(* Logix 5000 project; controller MOXA_SWITCH_DEMO vendor 1 type 14 code 77 rev 18.12; software revision 18.01 *)

TASK MainTask (continuous, watchdog 500 ms) : MainProgram

MODULES
   Controller : vendor 1 type 14 code 77 (CompactLogixL32EController 0, rev 18.12)
      LocalENB : 1769-L32E Ethernet Port (CompactLogixL32Ethernet 1, rev 18.11)
         MOXA_SWITCH : ETHERNET-MODULE (Ethernet 192.168.34.253, rev 1.1, Output RPI 10 ms)
      Local : CompactBus (CompactVirtualAdapter 3, rev 18.11)
END_MODULES

TYPE MOXA_Ethernet_Link_Object_v0 :   // class 0xf6
STRUCT
   Interface_Speed : DINT;   // Interface speed currently in use. Speed in Mbps (e.g., 0, 10, 100, 1000, etc.)
   Interface_Flags : MOXA_Interface_Object_Flags_v0;   // Interface status flags
   Physical_Address : SINT[6];   // MAC layer address
   InOctets : DINT;   // Octets received on the interface
   InUcastPackets : DINT;   // Unicast packets received on the interface
   InNucastPackets : DINT;   // Non-unicast packets received on the interface
   InDiscards : DINT;   // Inbound packets received on the interface but discarded
   InErrors : DINT;   // Inbound packets that contain errors (does not include In Discards)
   OutOctets : DINT;   // Octets sent on the interface
   OutUcastPackets : DINT;   // Unicast packets sent on the interface
   OutNucastPackets : DINT;   // Non-unicast packets sent on the interface
   OutDiscards : DINT;   // Outbound packets discarded
   OutErrors : DINT;   // Outbound packets that contain errors
   Alignment_Errors : DINT;   // Frames received that are not an integral number of octets in length
   FCS_Errors : DINT;   // Frames received that do not pass the FCS check
   Single_Collisions : DINT;   // Successfully transmitted frames which experienced exactly one collision
   Multiple_Collisions : DINT;   // Successfully transmitted frames which experienced more than one collision
   SQE_Test_Errors : DINT;   // Number of times SQE test error message is generated
   Deferred_Transmissions : DINT;   // Frames for which first transmission attempt is delayed because the medium is busy
   Late_Collisions : DINT;   // Number of times a collision is detected later than 512 bit- times into the transmission of a packet
   Excessive_Collisions : DINT;   // Frames for which transmission fails due to excessive collisions
   MAC_Transmit_Errors : DINT;   // Frames for which transmission fails due to an internal MAC sublayer transmit error
   Carrier_Sense_Errors : DINT;   // Times that the carrier sense condition was lost or never asserted when attempting to transmit a frame
   Frame_Too_Long : DINT;   // Frames received that exceed the maximum permitted frame size
   MAC_Receive_Errors : DINT;   // Frames for which reception on an interface fails due to an internal MAC sublayer receive error
   Control_Bits : INT;   // 0 Auto-negotiate 0 indicates 802.3 link auto-negotiation is disabled. 1 indicates auto-negotiation is enabled.
   Forced_Interface_Speed : INT;   // Speed at which the interface shall be forced to operate. Speed in Mbps (10, 100, 1000, etc.)
   Interface_Label : STRING;   // Label like "TX5"
   Interface_Port_Index : DINT;   // port index
   Interface_Port_Description : STRING;   // Port description
   Broascast_Storm_Protection : SINT;   // Only BCM
   Interface_Utilization : SINT;   // Percentage of entire interface bandwidth being used (0-100)
   Utilization_Alarm_Upper_Threshold : SINT;   // Upper percentage at which to declare a utilization alarm (0-100).
   Utilization_Alarm_Lower_Threshold : SINT;   // Lower percentage at which to declare a utilization alarm (0-100).
   Port_Link_Alarm : SINT;   // 0: Ignore 1:On (Relay 1) 2:On (Relay 2) 3:Off (Relay1) 4:Off (Relay2)
   Port_TrafficOverload_Alarm : SINT;   // 0:Disable 1:Enable(Relay 1) 2:Enable(Relay 2)
   Tx_Unicast_Packet_Rate : DINT;   // number of TX unicast packets per second.
   Rx_Unicast_Packet_Rate : DINT;   // number of RX unicast packets per second.
   Tx_Multicast_Packet_Rate : DINT;   // number of TX multicast packets per second.
   Rx_Multicast_Packet_Rate : DINT;   // number of RX multicast packets per second.
   Tx_Broadcast_Packet_Rate : DINT;   // number of TX broadcast packets per second.
   Rx_Broadcast_Packet_Rate : DINT;   // number of RX broadcast packets per second.
   Tx_Multicast_Packet : DINT;   // Total number of Tx multicast packets
   Rx_Multicast_Packet : DINT;   // Total number of Rx multicast packets
   Tx_Broadcast_Packet : DINT;   // Totalnumber of Tx Multicast packets
   Rx_Broadcast_Packet : DINT;   // Total number of Rx broadcast packets
   Redundant_Port_Status : DINT;   // Bit 0 = Disable, Bit 1 =Not Red. port, Bit 2 = Link down, Bit 3 = Blocking, Bit 4 = Learning, Bit 5 = Forwarding
END_STRUCT
END_TYPE

TYPE MOXA_HMI_Set_Object_v0 :
STRUCT
   Control_Bits : INT;
   Speed_Duplex : SINT;
   Port_Enable : SINT;   // 1=enable, 2=disable
   Enter_Port_Enable : BOOL;   // Set to 1 to trigger port enable/disable change
   Reset_mib_counter : SINT;   // reset mib counter
   Reset_to_default : SINT;   // Restart and reset to default
   Select_Port : INT;   // current port select on FT View
   Enter_Port_Setting : BOOL;
   Enter_Reset_Setting : BOOL;
END_STRUCT
END_TYPE

TYPE MOXA_Identity_Object_v0 :   // class 0x01
STRUCT
   Vendor_ID : INT;   // ODVA Vendor ID. N-Tron = 991
   Device_Type : INT;   // 0x307, "Managed Ethernet Switch"
   Product_Code : INT;   // EDS-405A=0x0006 EDS-408A=0x0007
   Major_Revision : SINT;   // Major revision of the item the Identity Object represents
   Minor_Revision : SINT;   // Minor revision of the item the Identity Object represents
   Serial_Number : DINT;   // Serial number of device
   Product_Name : STRING;   // Human readable identification. Switch model number. Ex: EDS-508A
   Assigned_Name : MOXA_String_1024;   // User assigned switch name.
   Geographic_Location : MOXA_String_1024;   // This is the user assigned switch location.
END_STRUCT
END_TYPE

TYPE MOXA_Interface_Object_Flags_v0 :   // reference to Ethernet Link object
STRUCT
   Link_Status : BOOL;   // 0-inactive, 1-active
   Duplex : BOOL;   // 0-half, 1-full
   Negotiation_Status_1 : BOOL;
   Negotiation_Status_2 : BOOL;
   Negotiation_Status_3 : BOOL;
   Manual_Setting_Requires_Reset : BOOL;
   Local_Hardware_Fault : BOOL;
END_STRUCT
END_TYPE

TYPE MOXA_Object_Data_v0 :   // This UDT contains various information that appears on an HMI display. Some information applies to the switch, and some applies to the selected port (copied, or derived from, the port Ethernet_Link data) because FactoryTalk can not access array elements.
STRUCT
   IP_Address : MOXA_String_32;
   Network_Mask : MOXA_String_32;
   Control_Bits : INT;
   Port_Speed : DINT;   // 1=10/half, 2=10/full, 3=100/half, 4=100/Full, 100=auto negotiate,
   Port_Interface_Flag : MOXA_Interface_Object_Flags_v0;
   MAC_Address : MOXA_String_32;
   Error_Counter : DINT;
   Port_Index : DINT;
   TX_Unicast_Packet_Rate : DINT;   // begin port specific data
   RX_Unicast_Packet_Rate : DINT;
   TX_Multicast_Packet_Rate : DINT;
   RX_Multicast_Packet_Rate : DINT;
   TX_Broadcast_Packet_Rate : DINT;
   RX_Broadcast_Packet_Rate : DINT;
   Redundant_Port_Role : DINT;   // redundant port role
   System_Fault : MOXA_System_Fault_v0;
   CPU_Usage : SINT;
   Redundant_Port_Status : DINT;   // bit 0: Disable Bit 1: Not Redundant Bit 2: Link down Bit 3: Blocking Bit 4: Learning Bit 5: Forwarding
   Software_Version : STRING;   // Show software version
   Port : INT;
   Interface_Utilization : SINT;
   Tx_Packet_Error : DINT;
   Rx_Packet_Error : DINT;
END_STRUCT
END_TYPE

TYPE MOXA_String_1024 :   // string type
STRUCT
   LEN : DINT;
   DATA : SINT[1024];
END_STRUCT
END_TYPE

TYPE MOXA_String_32 :   // string type; display the ip address, subnet mask, gateway address
STRUCT
   LEN : DINT;
   DATA : SINT[32];
END_STRUCT
END_TYPE

TYPE MOXA_Switch_In_v0 :   // switch input
STRUCT
   System_Fault : MOXA_System_Fault_v0;   // Status of various system faults.
   Link_Status : DINT;
   Link_Status_TX1 : BOOL;
   Link_Status_TX2 : BOOL;
   Link_Status_TX3 : BOOL;
   Link_Status_TX4 : BOOL;
   Link_Status_TX5 : BOOL;
   Link_Status_TX6 : BOOL;
   Link_Status_TX7 : BOOL;
   Link_Status_TX8 : BOOL;
   CPU_Utilization : SINT;   // Percent of CPU usage, 0-100
   Port_Exist : DINT;
   Port_Exist_1 : DINT;
   Port_Exist_2 : DINT;
   Port_Exist_3 : DINT;
   Port_Exist_4 : DINT;
   Port_Exist_5 : DINT;
   Port_Exist_6 : DINT;
   Port_Exist_7 : DINT;
   Port_Exist_8 : DINT;
END_STRUCT
END_TYPE

TYPE MOXA_Switch_Parameter :
STRUCT
   Switch_Input : MOXA_Switch_In_v0;   // recieve message from switch
   Switch_Output : DINT;   // send message from switch
   Switch_Idnetity : MOXA_Identity_Object_v0;
   Switch_TCPIP : MOXA_TCPIP_Interface_Object_v0;
   Switch_Vendor : MOXA_Vendor_Object_v0;
   Switch_Ethernet_Link : MOXA_Ethernet_Link_Object_v0[25];
   Switch_Data : MOXA_Object_Data_v0;
   Switch_HMI_Set : MOXA_HMI_Set_Object_v0;
END_STRUCT
END_TYPE

TYPE MOXA_System_Fault_v0 :   // reference to Switch object
STRUCT
   Fault : DINT;
   Turbo_Ring_Turbo_Ring_2 : BOOL;   // Reserved value 0: OK value 1: Fail
   Dongle_Configuration_Invalid : BOOL;   // Reserved value 0: OK value 1: Fail
   Port_Utilization_Alarm : BOOL;   // Value 0: no Alarm
   Port_Link_Up : BOOL;   // Value 0: no Alarm Value 1: Alarm
   Port_Link_Down : BOOL;   // Value 0: no Alarm Value 1: Alarm
   Turbo_Rinh_Break : BOOL;   // Ring Master Only Value 0: no Alarm Value 1: Alarm
   Power_Input_1_Fail : BOOL;   // Value 0: no Alarm Value 1: Alarm
   Power_Input_2_Fail : BOOL;   // Value 0: no Alarm Value 1: Alarm
   DI_1_Off : BOOL;   // Value 0: no Alarm Value 1: Alarm
   DI_1_On : BOOL;   // Value 0: no Alarm Value 1: Alarm
   DI_2_Off : BOOL;   // Value 0: no Alarm Value 1: Alarm
   DI_2_On : BOOL;   // Value 0: no Alarm Value 1: Alarm
   ABC_detect : BOOL;   // Value 0: no detect Value 1: detect
   Power_Supply_1 : BOOL;   // Value 0: off Value 1: on
   Power_Supply_2 : BOOL;   // Value 0: off Value 1: on
END_STRUCT
END_TYPE

TYPE MOXA_TCPIP_Interface_Object_v0 :   // class 0xf5
STRUCT
   Status : DINT;   // Interface Status:
   Configuration_Capability : DINT;   // Interface capability flags
   Configuration_Control : DINT;   // Interface control flags
   Path_Size : INT;   // Size of Path
   Object_Path_1 : INT;   // Logical segments identifying the physical link object
   Object_Path_2 : INT;   // Logical segments identifying the physical link object
   IP_Address : DINT;   // The device’s IP address.
   Network_Mask : DINT;   // The device’s network mask
   Gateway_Address : DINT;   // Default gateway address
   Name_Server_1 : DINT;   // Primary name server
   Name_Server_2 : DINT;   // Secondary name server
   Domain_Name : STRING;   // Default domain name
   Host_Name : STRING;   // Host Name
END_STRUCT
END_TYPE

TYPE MOXA_Vendor_Object_v0 :   // class 0x404
STRUCT
   System_Firmware_Version : DINT;   // Switch Firmware Version
   System_Fault_Status : DINT;   // Switch Fault Status
   Switch_Port_Number : SINT;   // Switch max port number
   Port_Exist : DINT[2];   // switch per port exist
   Port_Enbale : DINT[2];   // Switch Per Port Exist 0:Enable 1:Disable
   Port_Link_Status : DINT[2];   // Switch Per Port Link Status
   IGMP_Snooping : SINT;   // IGMP Snooping Enable: 0: disable 1: enable
   Query_Interval : DINT;   // Query Interval range from 20~600 sec
   IGMP_Enhanced_Mode : SINT;   // IGMP Enhanced Mode 0: Disable (default) 1: Enable
   Relay_1 : SINT;   // Override relay warning setting 0:Disable (default) 1: Enable
   Relay_2 : SINT;   // Override relay warning setting 0:Disable (default) 1: Enable
   Power_1_Relay_Warning : SINT;   // Power input 1 failure (on -> off) 0: Disable (default) 1: Enable(relay 1) 2: Enable(relay 2)
   Power_2_Relay_Warning : SINT;   // Power input 2 failure (on -> off) 0: Disable (default) 1: Enable(relay 1) 2: Enable(relay 2)
   DI_1_Off_Relay_Warning : SINT;   // DI 1 (off) 0: disable (default) 1: enable(relay 1) 2: enable(relay 2)
   DI_1_On_Relay_Warning : SINT;   // DI 1 (on) 0: disable (default) 1: enable(relay 1) 2: enable(relay 2)
   DI_2_Off_Relay_Warning : SINT;   // DI 2 (off) 0: disable (default) 1: enable(relay 1) 2: enable(relay 2)
   DI_2_On_Relay_Warning : SINT;   // DI 2 (on) 0: disable (default) 1: enable(relay 1) 2: enable(relay 2)
   Turbo_Ring_Break_Relay_Warning : SINT;   // Turbo Ring Break (Ring MAster Only ) 0: diable (default) 1: enable (relay 1) 2:enable (relay 2)
   CPU_Usage : SINT;   // Percent of usage (0-100)
   Device_Up_Time : DINT;   // Number of seconds since device was powered up.
   Reset_Mib_Counter : SINT;   // Reset port MIB counters.
   Redundant_Device_Mode : DINT;   // Bit 0: RSTP Bit 1: turbo ring Bit 2: turbo ring v2 Bit 3: turbo chain Bit 4: MSTP
END_STRUCT
END_TYPE

ADD_ON_INSTRUCTION AOI_MOXA_SWITCH_v1_0_0   (* revision 1.0, vendor MOXA Corporation *)
// the AOI of MOXA switch
// Copyright MOXA Corp. 2011
// Version: 1.0.0
// Date: December 23, 2011
VAR_IN_OUT
   Switch_Input : DINT[5]; {required}   // The module defined array representing the input assembly
   Switch_Output : DINT[1]; {required}   // The module defined array representing the output assembly
   Switch_Parameter : MOXA_Switch_Parameter; {required}
   Get_AllMessage : MESSAGE; {required}   // Message to retrieve parameters from CIP object what service is get all
   Set_Message : MESSAGE; {required}   // Message to send parameters from CIP object
   storage : SINT[200]; {required}   // Internal use: storage for explicit messaging responses
   Set_Data : INT[2]; {required}
   Get_SingMessage : MESSAGE; {required}   // Message to retrieve parameters from CIP object what service is get single
   storage_single : SINT[70]; {required}
END_VAR
VAR
   copyTimer : TIMER := (PRE := 5000); {access None}   // for loop every 5 sec
   timer_io : TIMER := (PRE := 50); {access None}
   SelectCounter : COUNTER := (PRE := 150); {access None}
   port_index : DINT; {access None}
   IP_Address_StringArray : STRING[4]; {access None}
   Network_Mask_StringArray : STRING[4]; {access None}
   IP_Address_OctetArray : DINT[4]; {access None}
   Network_Mask_OctetArray : DINT[4]; {access None}
   MAC_OctetArray : DINT[12]; {access None}
   MAC_StringArray : STRING[12]; {access None}
   timer_explicit : TIMER := (PRE := 100); {access None}
   Update_flag : BOOL; {access None}   // Update flag. start to read MSG
   punctuation_marks : STRING; {access None}
   String_Len : DINT;
   GetVendorObject : INT;
   portnum_index : SINT;
   Port_Enable_setting : INT; {access None}
   AttriSelectCounter : INT; {access None}
   Firmware_Version_Object : DINT;
   ons_getall : BOOL; {access None}
   ons_getsingle : BOOL; {access None}
   Debug : DINT; {access None}
   timer_ethernet : TIMER := (PRE := 200); {access None}
   temp_data : DINT;
   MAC_Counter : DINT; {access None}
   b_SetPortMSG : BOOL; {access None}
   b_SetMibMSG : BOOL; {access None}
   b_SetResetMSG : BOOL; {access None}
   Software_Version_temp : SINT[2]; {access None}
   Software_Version_String : STRING[2]; {access None}
   b_SetPortEnable : BOOL; {access None}
   b_SetPortDuplex : BOOL; {access None}
   InterfaceControlBit : INT; {access None}
   InterfaceSpeedDuplex : INT; {access None}
   b_SetMSG : BOOL; {access None}
   InterfacePortEnable : INT; {access None}
END_VAR

ROUTINE Logic   (* ladder *)
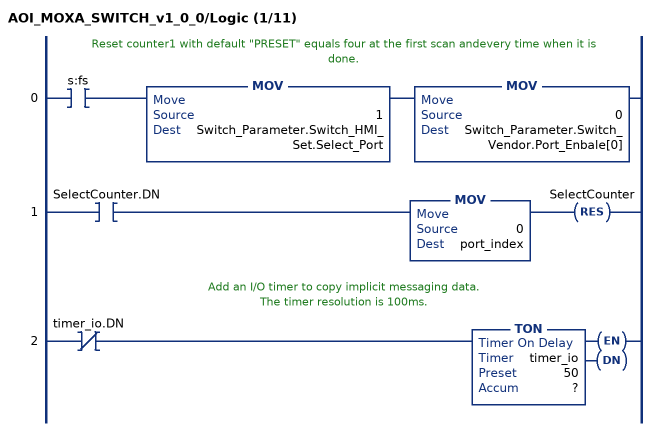
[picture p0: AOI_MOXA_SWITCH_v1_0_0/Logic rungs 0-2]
   // Reset counter1 with default "PRESET" equals four at the first scan andevery time when it is done.
   0: XIC(s:fs)MOV(1,Switch_Parameter.Switch_HMI_Set.Select_Port)MOV(0,Switch_Parameter.Switch_Vendor.Port_Enbale[0]);
   1: XIC(SelectCounter.DN)MOV(0,port_index)RES(SelectCounter);
   // Add an I/O timer to copy implicit messaging data.
   // The timer resolution is 100ms.
   2: XIO(timer_io.DN)TON(timer_io,?,?);
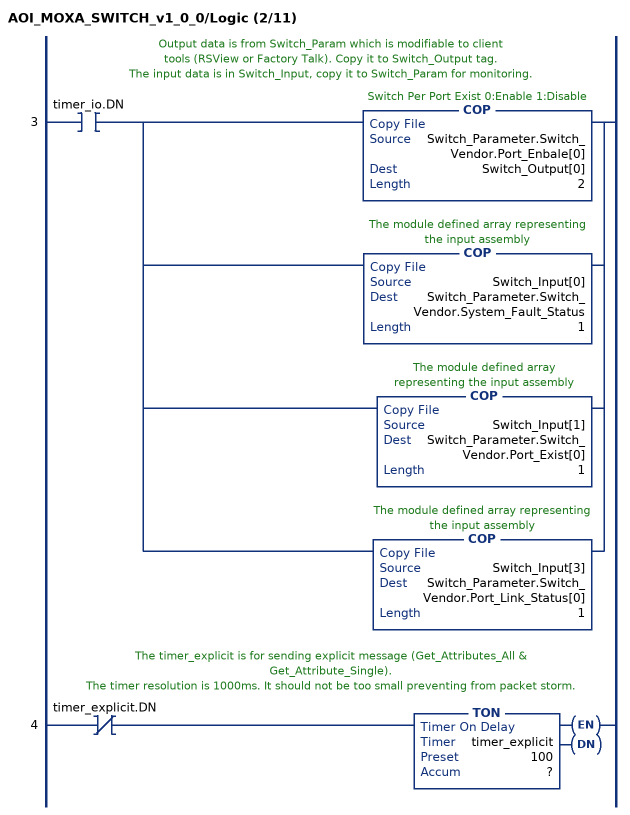
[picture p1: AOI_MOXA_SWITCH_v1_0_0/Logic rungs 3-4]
   // Output data is from Switch_Param which is modifiable to client
   //  tools (RSView or Factory Talk). Copy it to Switch_Output tag.
   // The input data is in Switch_Input, copy it to Switch_Param for monitoring.
   3: XIC(timer_io.DN)[COP(Switch_Parameter.Switch_Vendor.Port_Enbale[0],Switch_Output[0],2) ,COP(Switch_Input[0],Switch_Parameter.Switch_Vendor.System_Fault_Status,1) ,COP(Switch_Input[1],Switch_Parameter.Switch_Vendor.Port_Exist[0],1) ,COP(Switch_Input[3],Switch_Parameter.Switch_Vendor.Port_Link_Status[0],1) ];
   // The timer_explicit is for sending explicit message (Get_Attributes_All & Get_Attribute_Single).
   // The timer resolution is 1000ms. It should not be too small preventing from packet storm.
   4: XIO(timer_explicit.DN)TON(timer_explicit,?,?);
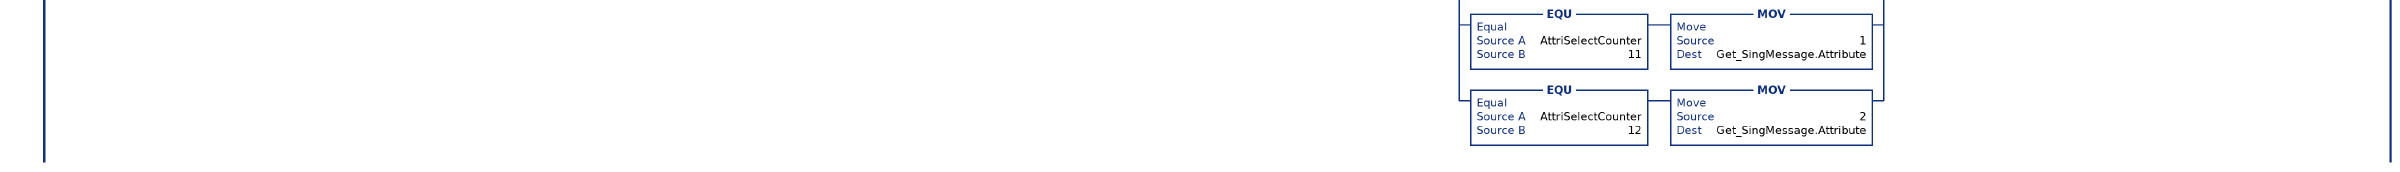
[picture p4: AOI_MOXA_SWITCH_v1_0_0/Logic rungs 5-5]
   // If ClassSelectCounter.ACC== 1, send GAA of Identity object (Class ID = 1).
   // If ClassSelectCounter.ACC== 2, send GAA of TCP/IP object (Class ID = 245).
   // If ClassSelectCounter.ACC== 3, send GAA of Vendor object (class ID = 1028)
   // If ClassSelectCounter.ACC==4~15, snd GAA of Ethernet Link object(Class ID = 246)
   5: XIC(timer_explicit.DN)CTU(SelectCounter,?,?)[LIM(1,SelectCounter.ACC,2) MOV(1,Get_AllMessage.Instance) MOV(1,Get_AllMessage.Attribute) [EQU(SelectCounter.ACC,1) MOV(1,Get_AllMessage.Class) ,EQU(SelectCounter.ACC,2) MOV(245,Get_AllMessage.Class) ] FLL(0,storage[0],200) MSG(Get_AllMessage) ,LIM(3,SelectCounter.ACC,11) MOV(1028,Get_SingMessage.Class) MOV(1,Get_SingMessage.Instance) [EQU(SelectCounter.ACC,3) MOV(1,Get_SingMessage.Attribute) ,EQU(SelectCounter.ACC,4) MOV(2,Get_SingMessage.Attribute) ,EQU(SelectCounter.ACC,5) MOV(5,Get_SingMessage.Attribute) ,EQU(SelectCounter.ACC,6) MOV(6,Get_SingMessage.Attribute) ,EQU(SelectCounter.ACC,7) MOV(8,Get_SingMessage.Attribute) ,EQU(SelectCounter.ACC,8) MOV(9,Get_SingMessage.Attribute) ,EQU(SelectCounter.ACC,9) MOV(23,Get_SingMessage.Attribute) ,EQU(SelectCounter.ACC,10) MOV(25,Get_SingMessage.Attribute) ,EQU(SelectCounter.ACC,11) MOV(26,Get_SingMessage.Attribute) ] FLL(0,storage[0],200) MSG(Get_SingMessage) ,LIM(12,SelectCounter.ACC,150) SUB(SelectCounter.ACC,12,AttriSelectCounter) DIV(AttriSelectCounter,13,temp_data) ADD(temp_data,1,portnum_index) MOD(AttriSelectCounter,13,AttriSelectCounter) MOV(246,Get_SingMessage.Class) MOV(portnum_index,Get_SingMessage.Instance) [EQU(AttriSelectCounter,0) MOV(3,Get_SingMessage.Attribute) ,EQU(AttriSelectCounter,1) MOV(4,Get_SingMessage.Attribute) ,EQU(AttriSelectCounter,2) MOV(6,Get_SingMessage.Attribute) ,EQU(AttriSelectCounter,3) MOV(103,Get_SingMessage.Attribute) ,EQU(AttriSelectCounter,4) MOV(108,Get_SingMessage.Attribute) ,EQU(AttriSelectCounter,5) MOV(109,Get_SingMessage.Attribute) ,EQU(AttriSelectCounter,6) MOV(110,Get_SingMessage.Attribute) ,EQU(AttriSelectCounter,7) MOV(111,Get_SingMessage.Attribute) ,EQU(AttriSelectCounter,8) MOV(112,Get_SingMessage.Attribute) ,EQU(AttriSelectCounter,9) MOV(113,Get_SingMessage.Attribute) ,EQU(AttriSelectCounter,10) MOV(118,Get_SingMessage.Attribute) ,EQU(AttriSelectCounter,11) MOV(1,Get_SingMessage.Attribute) ,EQU(AttriSelectCounter,12) MOV(2,Get_SingMessage.Attribute) ] FLL(0,storage_single[0],70) MSG(Get_SingMessage) ];
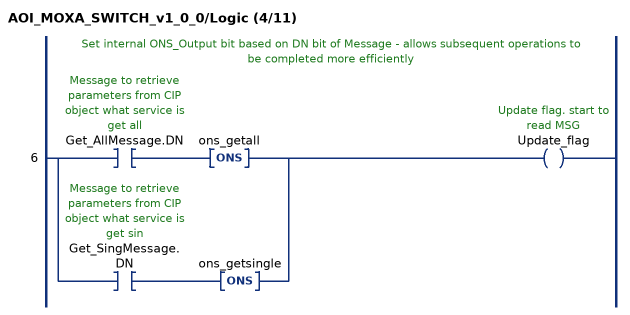
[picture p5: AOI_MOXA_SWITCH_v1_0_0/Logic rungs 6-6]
   // Set internal ONS_Output bit based on DN bit of Message - allows subsequent operations to be completed more efficiently
   6: [XIC(Get_AllMessage.DN) ONS(ons_getall) ,XIC(Get_SingMessage.DN) ONS(ons_getsingle) ]OTE(Update_flag);
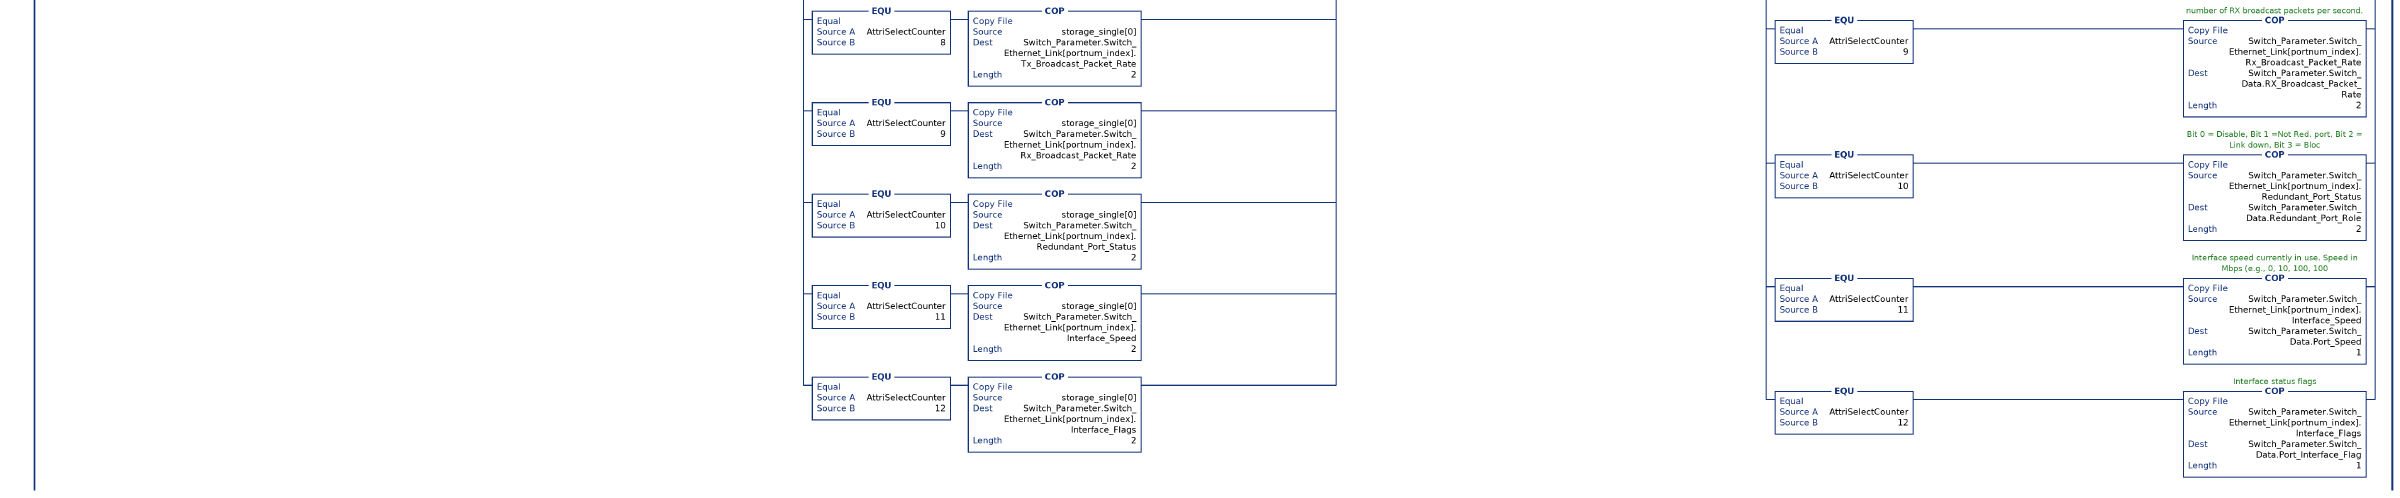
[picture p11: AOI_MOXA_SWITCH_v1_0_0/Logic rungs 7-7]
   // Copy results of Get Attribute All
   // If counter = 1: Identity Object - Class 1, Instance 1, Attribute 1
   // If counter = 2: TCP/IP Interface Object, Class 245, Instance 1, Attribute 1
   // If counter = 3 : Vendor Object, Class 1028, Instance 1, Attribute 1
   // If counter = 4~15 : EtherNet Link Object, Class 246, Instance 1 to 12 , Attribute 1 - EthernetLink[1-12]
   7: XIC(Update_flag)[EQU(SelectCounter.ACC,1) [COP(storage[0],Switch_Parameter.Switch_Idnetity.Vendor_ID,1) ,COP(storage[2],Switch_Parameter.Switch_Idnetity.Device_Type,1) ,COP(storage[4],Switch_Parameter.Switch_Idnetity.Product_Code,1) ,COP(storage[10],Switch_Parameter.Switch_Idnetity.Serial_Number,2) ,MOV(storage[14],String_Len) MOV(String_Len,Switch_Parameter.Switch_Idnetity.Product_Name.LEN) FLL(0,Switch_Parameter.Switch_Idnetity.Product_Name.DATA[0],28) COP(storage[15],Switch_Parameter.Switch_Idnetity.Product_Name.DATA[0],String_Len) ] ,EQU(SelectCounter.ACC,2) [COP(storage[18],Switch_Parameter.Switch_TCPIP.IP_Address,2) ,COP(storage[22],Switch_Parameter.Switch_TCPIP.Network_Mask,2) ,MOV(0,String_Len) COP(storage[38],String_Len,1) ADD(String_Len,40,String_Len) ,COP(storage[40],Switch_Parameter.Switch_TCPIP.Host_Name.LEN,1) ADD(String_Len,2,String_Len) ,COP(storage[42],Switch_Parameter.Switch_TCPIP.Host_Name.DATA[0],64) ] ,LIM(3,SelectCounter.ACC,11) [EQU(SelectCounter.ACC,3) COP(storage_single[0],Switch_Parameter.Switch_Vendor.System_Firmware_Version,2) ,EQU(SelectCounter.ACC,4) COP(storage_single[0],Switch_Parameter.Switch_Vendor.System_Fault_Status,2) ,EQU(SelectCounter.ACC,5) COP(storage_single[0],Switch_Parameter.Switch_Vendor.Port_Enbale[0],4) ,EQU(SelectCounter.ACC,6) COP(storage_single[0],Switch_Parameter.Switch_Vendor.Port_Link_Status[0],4) ,EQU(SelectCounter.ACC,7) COP(storage_single[0],Switch_Parameter.Switch_Vendor.Query_Interval,2) ,EQU(SelectCounter.ACC,8) COP(storage_single[0],Switch_Parameter.Switch_Vendor.IGMP_Enhanced_Mode,1) ,EQU(SelectCounter.ACC,9) COP(storage_single[0],Switch_Parameter.Switch_Vendor.CPU_Usage,1) ,EQU(SelectCounter.ACC,10) COP(storage_single[0],Switch_Parameter.Switch_Vendor.Reset_Mib_Counter,1) ,EQU(SelectCounter.ACC,11) COP(storage_single[0],Switch_Parameter.Switch_Vendor.Redundant_Device_Mode,2) ] ,LIM(12,SelectCounter.ACC,150) SUB(SelectCounter.ACC,12,AttriSelectCounter) DIV(AttriSelectCounter,13,temp_data) ADD(temp_data,1,portnum_index) MOD(AttriSelectCounter,13,AttriSelectCounter) [EQU(AttriSelectCounter,0) COP(storage_single[0],Switch_Parameter.Switch_Ethernet_Link[portnum_index].Physical_Address[0],6) ,EQU(AttriSelectCounter,1) [COP(storage_single[16],Switch_Parameter.Switch_Ethernet_Link[portnum_index].InErrors,2) ,COP(storage_single[40],Switch_Parameter.Switch_Ethernet_Link[portnum_index].OutErrors,2) ] ,EQU(AttriSelectCounter,2) [LIM(0,storage_single[0],2) COP(storage_single[0],Switch_Parameter.Switch_Ethernet_Link[portnum_index].Control_Bits,1) ,[EQU(storage_single[2],0) ,EQU(storage_single[2],10) ,EQU(storage_single[2],100) ,EQU(storage_single[2],1000) ] COP(storage_single[2],Switch_Parameter.Switch_Ethernet_Link[portnum_index].Forced_Interface_Speed,1) ] ,EQU(AttriSelectCounter,3) COP(storage_single[0],Switch_Parameter.Switch_Ethernet_Link[portnum_index].Interface_Utilization,1) ,EQU(AttriSelectCounter,4) COP(storage_single[0],Switch_Parameter.Switch_Ethernet_Link[portnum_index].Tx_Unicast_Packet_Rate,1) ,EQU(AttriSelectCounter,5) COP(storage_single[0],Switch_Parameter.Switch_Ethernet_Link[portnum_index].Rx_Unicast_Packet_Rate,1) ,EQU(AttriSelectCounter,6) COP(storage_single[0],Switch_Parameter.Switch_Ethernet_Link[portnum_index].Tx_Multicast_Packet_Rate,2) ,EQU(AttriSelectCounter,7) COP(storage_single[0],Switch_Parameter.Switch_Ethernet_Link[portnum_index].Rx_Multicast_Packet_Rate,2) ,EQU(AttriSelectCounter,8) COP(storage_single[0],Switch_Parameter.Switch_Ethernet_Link[portnum_index].Tx_Broadcast_Packet_Rate,2) ,EQU(AttriSelectCounter,9) COP(storage_single[0],Switch_Parameter.Switch_Ethernet_Link[portnum_index].Rx_Broadcast_Packet_Rate,2) ,EQU(AttriSelectCounter,10) COP(storage_single[0],Switch_Parameter.Switch_Ethernet_Link[portnum_index].Redundant_Port_Status,2) ,EQU(AttriSelectCounter,11) COP(storage_single[0],Switch_Parameter.Switch_Ethernet_Link[portnum_index].Interface_Speed,2) ,EQU(AttriSelectCounter,12) COP(storage_single[0],Switch_Parameter.Switch_Ethernet_Link[portnum_index].Interface_Flags,2) ] EQU(Switch_Parameter.Switch_HMI_Set.Select_Port,portnum_index) MOV(Switch_Parameter.Switch_HMI_Set.Select_Port,Switch_Parameter.Switch_Data.Port) [EQU(AttriSelectCounter,1) [COP(Switch_Parameter.Switch_Ethernet_Link[portnum_index].InErrors,Switch_Parameter.Switch_Data.Error_Counter,2) ADD(Switch_Parameter.Switch_Ethernet_Link[portnum_index].OutErrors,Switch_Parameter.Switch_Data.Error_Counter,Switch_Parameter.Switch_Data.Error_Counter) ,COP(Switch_Parameter.Switch_Ethernet_Link[portnum_index].InErrors,Switch_Parameter.Switch_Data.Rx_Packet_Error,2) COP(Switch_Parameter.Switch_Ethernet_Link[portnum_index].OutErrors,Switch_Parameter.Switch_Data.Rx_Packet_Error,2) ] ,EQU(AttriSelectCounter,2) COP(Switch_Parameter.Switch_Ethernet_Link[portnum_index].Control_Bits,Switch_Parameter.Switch_Data.Control_Bits,1) ,EQU(AttriSelectCounter,3) COP(Switch_Parameter.Switch_Ethernet_Link[portnum_index].Interface_Utilization,Switch_Parameter.Switch_Data.Interface_Utilization,1) ,EQU(AttriSelectCounter,4) COP(Switch_Parameter.Switch_Ethernet_Link[portnum_index].Tx_Unicast_Packet_Rate,Switch_Parameter.Switch_Data.TX_Unicast_Packet_Rate,2) ,EQU(AttriSelectCounter,5) COP(Switch_Parameter.Switch_Ethernet_Link[portnum_index].Rx_Unicast_Packet_Rate,Switch_Parameter.Switch_Data.RX_Unicast_Packet_Rate,2) ,EQU(AttriSelectCounter,6) COP(Switch_Parameter.Switch_Ethernet_Link[portnum_index].Tx_Multicast_Packet_Rate,Switch_Parameter.Switch_Data.TX_Multicast_Packet_Rate,2) ,EQU(AttriSelectCounter,7) COP(Switch_Parameter.Switch_Ethernet_Link[portnum_index].Rx_Multicast_Packet_Rate,Switch_Parameter.Switch_Data.RX_Multicast_Packet_Rate,2) ,EQU(AttriSelectCounter,8) COP(Switch_Parameter.Switch_Ethernet_Link[portnum_index].Tx_Broadcast_Packet_Rate,Switch_Parameter.Switch_Data.TX_Broadcast_Packet_Rate,2) ,EQU(AttriSelectCounter,9) COP(Switch_Parameter.Switch_Ethernet_Link[portnum_index].Rx_Broadcast_Packet_Rate,Switch_Parameter.Switch_Data.RX_Broadcast_Packet_Rate,2) ,EQU(AttriSelectCounter,10) COP(Switch_Parameter.Switch_Ethernet_Link[portnum_index].Redundant_Port_Status,Switch_Parameter.Switch_Data.Redundant_Port_Role,2) ,EQU(AttriSelectCounter,11) COP(Switch_Parameter.Switch_Ethernet_Link[portnum_index].Interface_Speed,Switch_Parameter.Switch_Data.Port_Speed,1) ,EQU(AttriSelectCounter,12) COP(Switch_Parameter.Switch_Ethernet_Link[portnum_index].Interface_Flags,Switch_Parameter.Switch_Data.Port_Interface_Flag,1) ] ];
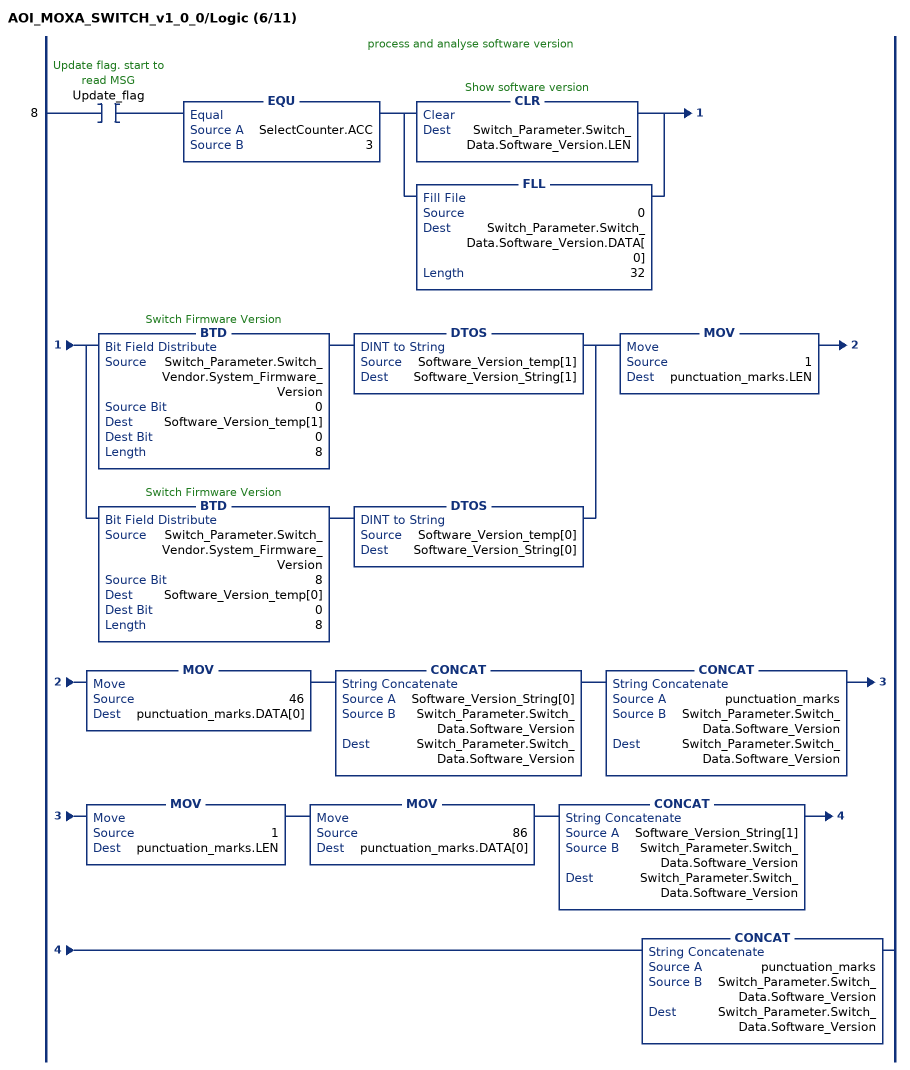
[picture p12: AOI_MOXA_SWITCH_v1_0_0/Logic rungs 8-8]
   // process and analyse software version
   8: XIC(Update_flag)EQU(SelectCounter.ACC,3)[CLR(Switch_Parameter.Switch_Data.Software_Version.LEN) ,FLL(0,Switch_Parameter.Switch_Data.Software_Version.DATA[0],32) ][BTD(Switch_Parameter.Switch_Vendor.System_Firmware_Version,0,Software_Version_temp[1],0,8) DTOS(Software_Version_temp[1],Software_Version_String[1]) ,BTD(Switch_Parameter.Switch_Vendor.System_Firmware_Version,8,Software_Version_temp[0],0,8) DTOS(Software_Version_temp[0],Software_Version_String[0]) ]MOV(1,punctuation_marks.LEN)MOV(46,punctuation_marks.DATA[0])CONCAT(Software_Version_String[0],Switch_Parameter.Switch_Data.Software_Version,Switch_Parameter.Switch_Data.Software_Version)CONCAT(punctuation_marks,Switch_Parameter.Switch_Data.Software_Version,Switch_Parameter.Switch_Data.Software_Version)MOV(1,punctuation_marks.LEN)MOV(86,punctuation_marks.DATA[0])CONCAT(Software_Version_String[1],Switch_Parameter.Switch_Data.Software_Version,Switch_Parameter.Switch_Data.Software_Version)CONCAT(punctuation_marks,Switch_Parameter.Switch_Data.Software_Version,Switch_Parameter.Switch_Data.Software_Version);
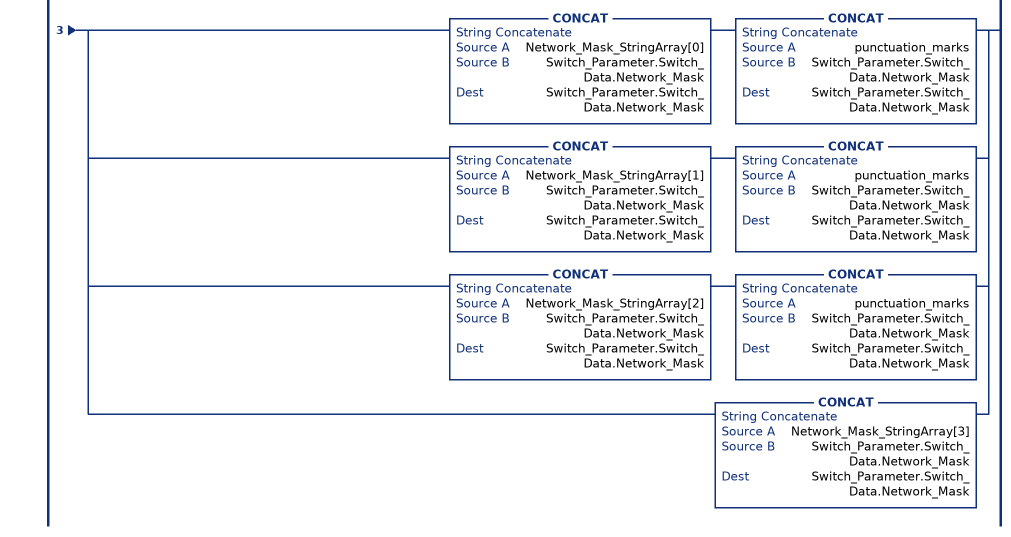
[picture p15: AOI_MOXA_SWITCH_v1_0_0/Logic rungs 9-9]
   // process and analyse IP address and subnet data and convert the data type from the integer to the string
   9: XIC(Update_flag)EQU(SelectCounter.ACC,2)[CLR(Switch_Parameter.Switch_Data.IP_Address.LEN) ,FLL(0,Switch_Parameter.Switch_Data.IP_Address.DATA[0],32) ][CLR(Switch_Parameter.Switch_Data.Network_Mask.LEN) ,FLL(0,Switch_Parameter.Switch_Data.Network_Mask.DATA[0],32) ][BTD(Switch_Parameter.Switch_TCPIP.IP_Address,0,IP_Address_OctetArray[0],0,8) ,BTD(Switch_Parameter.Switch_TCPIP.IP_Address,8,IP_Address_OctetArray[1],0,8) ,BTD(Switch_Parameter.Switch_TCPIP.IP_Address,16,IP_Address_OctetArray[2],0,8) ,BTD(Switch_Parameter.Switch_TCPIP.IP_Address,24,IP_Address_OctetArray[3],0,8) ,BTD(Switch_Parameter.Switch_TCPIP.Network_Mask,0,Network_Mask_OctetArray[0],0,8) ,BTD(Switch_Parameter.Switch_TCPIP.Network_Mask,8,Network_Mask_OctetArray[1],0,8) ,BTD(Switch_Parameter.Switch_TCPIP.Network_Mask,16,Network_Mask_OctetArray[2],0,8) ,BTD(Switch_Parameter.Switch_TCPIP.Network_Mask,24,Network_Mask_OctetArray[3],0,8) ][DTOS(IP_Address_OctetArray[0],IP_Address_StringArray[0]) ,DTOS(IP_Address_OctetArray[1],IP_Address_StringArray[1]) ,DTOS(IP_Address_OctetArray[2],IP_Address_StringArray[2]) ,DTOS(IP_Address_OctetArray[3],IP_Address_StringArray[3]) ,DTOS(Network_Mask_OctetArray[0],Network_Mask_StringArray[0]) ,DTOS(Network_Mask_OctetArray[1],Network_Mask_StringArray[1]) ,DTOS(Network_Mask_OctetArray[2],Network_Mask_StringArray[2]) ,DTOS(Network_Mask_OctetArray[3],Network_Mask_StringArray[3]) ]MOV(1,punctuation_marks.LEN)MOV(46,punctuation_marks.DATA[0])[CONCAT(IP_Address_StringArray[0],Switch_Parameter.Switch_Data.IP_Address,Switch_Parameter.Switch_Data.IP_Address) CONCAT(punctuation_marks,Switch_Parameter.Switch_Data.IP_Address,Switch_Parameter.Switch_Data.IP_Address) ,CONCAT(IP_Address_StringArray[1],Switch_Parameter.Switch_Data.IP_Address,Switch_Parameter.Switch_Data.IP_Address) CONCAT(punctuation_marks,Switch_Parameter.Switch_Data.IP_Address,Switch_Parameter.Switch_Data.IP_Address) ,CONCAT(IP_Address_StringArray[2],Switch_Parameter.Switch_Data.IP_Address,Switch_Parameter.Switch_Data.IP_Address) CONCAT(punctuation_marks,Switch_Parameter.Switch_Data.IP_Address,Switch_Parameter.Switch_Data.IP_Address) ,CONCAT(IP_Address_StringArray[3],Switch_Parameter.Switch_Data.IP_Address,Switch_Parameter.Switch_Data.IP_Address) ][CONCAT(Network_Mask_StringArray[0],Switch_Parameter.Switch_Data.Network_Mask,Switch_Parameter.Switch_Data.Network_Mask) CONCAT(punctuation_marks,Switch_Parameter.Switch_Data.Network_Mask,Switch_Parameter.Switch_Data.Network_Mask) ,CONCAT(Network_Mask_StringArray[1],Switch_Parameter.Switch_Data.Network_Mask,Switch_Parameter.Switch_Data.Network_Mask) CONCAT(punctuation_marks,Switch_Parameter.Switch_Data.Network_Mask,Switch_Parameter.Switch_Data.Network_Mask) ,CONCAT(Network_Mask_StringArray[2],Switch_Parameter.Switch_Data.Network_Mask,Switch_Parameter.Switch_Data.Network_Mask) CONCAT(punctuation_marks,Switch_Parameter.Switch_Data.Network_Mask,Switch_Parameter.Switch_Data.Network_Mask) ,CONCAT(Network_Mask_StringArray[3],Switch_Parameter.Switch_Data.Network_Mask,Switch_Parameter.Switch_Data.Network_Mask) ];
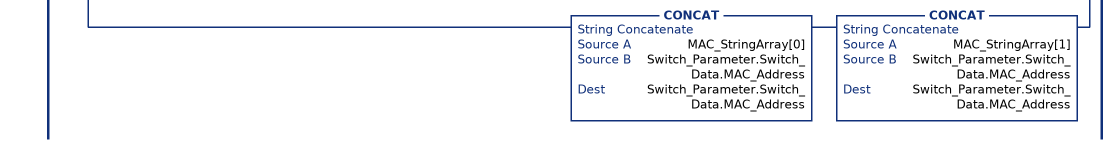
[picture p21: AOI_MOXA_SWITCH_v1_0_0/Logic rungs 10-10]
   // process and analyse MAC address and convert the data type from the integer to the string
   10: XIC(Update_flag)EQU(SelectCounter.ACC,12)[CLR(Switch_Parameter.Switch_Data.MAC_Address.LEN) ,FLL(0,Switch_Parameter.Switch_Data.MAC_Address.DATA[0],32) ][BTD(Switch_Parameter.Switch_Ethernet_Link[1].Physical_Address[0],0,MAC_OctetArray[0],0,4) BTD(Switch_Parameter.Switch_Ethernet_Link[1].Physical_Address[0],4,MAC_OctetArray[1],0,4) ,BTD(Switch_Parameter.Switch_Ethernet_Link[1].Physical_Address[1],0,MAC_OctetArray[2],0,4) BTD(Switch_Parameter.Switch_Ethernet_Link[1].Physical_Address[1],4,MAC_OctetArray[3],0,4) ,BTD(Switch_Parameter.Switch_Ethernet_Link[1].Physical_Address[2],0,MAC_OctetArray[4],0,4) BTD(Switch_Parameter.Switch_Ethernet_Link[1].Physical_Address[2],4,MAC_OctetArray[5],0,4) ,BTD(Switch_Parameter.Switch_Ethernet_Link[1].Physical_Address[3],0,MAC_OctetArray[6],0,4) BTD(Switch_Parameter.Switch_Ethernet_Link[1].Physical_Address[3],4,MAC_OctetArray[7],0,4) ,BTD(Switch_Parameter.Switch_Ethernet_Link[1].Physical_Address[4],0,MAC_OctetArray[8],0,4) BTD(Switch_Parameter.Switch_Ethernet_Link[1].Physical_Address[4],4,MAC_OctetArray[9],0,4) ,BTD(Switch_Parameter.Switch_Ethernet_Link[1].Physical_Address[5],0,MAC_OctetArray[10],0,4) BTD(Switch_Parameter.Switch_Ethernet_Link[1].Physical_Address[5],4,MAC_OctetArray[11],0,4) ][[LIM(0,MAC_OctetArray[0],9) DTOS(MAC_OctetArray[0],MAC_StringArray[0]) ,LIM(10,MAC_OctetArray[0],15) [MOV(1,MAC_StringArray[0].LEN) ,CPT(MAC_StringArray[0].DATA[0],MAC_OctetArray[0]+55) ] ] ,[LIM(0,MAC_OctetArray[1],9) DTOS(MAC_OctetArray[1],MAC_StringArray[1]) ,LIM(10,MAC_OctetArray[1],15) [MOV(1,MAC_StringArray[1].LEN) ,CPT(MAC_StringArray[1].DATA[0],MAC_OctetArray[1]+55) ] ] ,[LIM(0,MAC_OctetArray[2],9) DTOS(MAC_OctetArray[2],MAC_StringArray[2]) ,LIM(10,MAC_OctetArray[2],15) [MOV(1,MAC_StringArray[2].LEN) ,CPT(MAC_StringArray[2].DATA[0],MAC_OctetArray[2]+55) ] ] ,[LIM(0,MAC_OctetArray[3],9) DTOS(MAC_OctetArray[3],MAC_StringArray[3]) ,LIM(10,MAC_OctetArray[3],15) [MOV(1,MAC_StringArray[3].LEN) ,CPT(MAC_StringArray[3].DATA[0],MAC_OctetArray[3]+55) ] ] ,[LIM(0,MAC_OctetArray[4],9) DTOS(MAC_OctetArray[4],MAC_StringArray[4]) ,LIM(10,MAC_OctetArray[4],15) [MOV(1,MAC_StringArray[4].LEN) ,CPT(MAC_StringArray[4].DATA[0],MAC_OctetArray[4]+55) ] ] ,[LIM(0,MAC_OctetArray[5],9) DTOS(MAC_OctetArray[5],MAC_StringArray[5]) ,LIM(10,MAC_OctetArray[5],15) [MOV(1,MAC_StringArray[5].LEN) ,CPT(MAC_StringArray[5].DATA[0],MAC_OctetArray[5]+55) ] ] ,[LIM(0,MAC_OctetArray[6],9) DTOS(MAC_OctetArray[6],MAC_StringArray[6]) ,LIM(10,MAC_OctetArray[6],15) [MOV(1,MAC_StringArray[6].LEN) ,CPT(MAC_StringArray[6].DATA[0],MAC_OctetArray[6]+55) ] ] ,[LIM(0,MAC_OctetArray[7],9) DTOS(MAC_OctetArray[7],MAC_StringArray[7]) ,LIM(10,MAC_OctetArray[7],15) [MOV(1,MAC_StringArray[7].LEN) ,CPT(MAC_StringArray[7].DATA[0],MAC_OctetArray[7]+55) ] ] ,[LIM(0,MAC_OctetArray[8],9) DTOS(MAC_OctetArray[8],MAC_StringArray[8]) ,LIM(10,MAC_OctetArray[8],15) [MOV(1,MAC_StringArray[8].LEN) ,CPT(MAC_StringArray[8].DATA[0],MAC_OctetArray[8]+55) ] ] ,[LIM(0,MAC_OctetArray[9],9) DTOS(MAC_OctetArray[9],MAC_StringArray[9]) ,LIM(10,MAC_OctetArray[9],15) [MOV(1,MAC_StringArray[9].LEN) ,CPT(MAC_StringArray[9].DATA[0],MAC_OctetArray[9]+55) ] ] ,[LIM(0,MAC_OctetArray[10],9) DTOS(MAC_OctetArray[10],MAC_StringArray[10]) ,LIM(10,MAC_OctetArray[10],15) [MOV(1,MAC_StringArray[10].LEN) ,CPT(MAC_StringArray[10].DATA[0],MAC_OctetArray[10]+55) ] ] ,[LIM(0,MAC_OctetArray[11],9) DTOS(MAC_OctetArray[11],MAC_StringArray[11]) ,LIM(10,MAC_OctetArray[11],15) [MOV(1,MAC_StringArray[11].LEN) ,CPT(MAC_StringArray[11].DATA[0],MAC_OctetArray[11]+55) ] ] ]MOV(1,punctuation_marks.LEN)MOV(45,punctuation_marks.DATA[0])[CONCAT(MAC_StringArray[10],Switch_Parameter.Switch_Data.MAC_Address,Switch_Parameter.Switch_Data.MAC_Address) CONCAT(MAC_StringArray[11],Switch_Parameter.Switch_Data.MAC_Address,Switch_Parameter.Switch_Data.MAC_Address) CONCAT(punctuation_marks,Switch_Parameter.Switch_Data.MAC_Address,Switch_Parameter.Switch_Data.MAC_Address) ,CONCAT(MAC_StringArray[8],Switch_Parameter.Switch_Data.MAC_Address,Switch_Parameter.Switch_Data.MAC_Address) CONCAT(MAC_StringArray[9],Switch_Parameter.Switch_Data.MAC_Address,Switch_Parameter.Switch_Data.MAC_Address) CONCAT(punctuation_marks,Switch_Parameter.Switch_Data.MAC_Address,Switch_Parameter.Switch_Data.MAC_Address) ,CONCAT(MAC_StringArray[6],Switch_Parameter.Switch_Data.MAC_Address,Switch_Parameter.Switch_Data.MAC_Address) CONCAT(MAC_StringArray[7],Switch_Parameter.Switch_Data.MAC_Address,Switch_Parameter.Switch_Data.MAC_Address) CONCAT(punctuation_marks,Switch_Parameter.Switch_Data.MAC_Address,Switch_Parameter.Switch_Data.MAC_Address) ,CONCAT(MAC_StringArray[4],Switch_Parameter.Switch_Data.MAC_Address,Switch_Parameter.Switch_Data.MAC_Address) CONCAT(MAC_StringArray[5],Switch_Parameter.Switch_Data.MAC_Address,Switch_Parameter.Switch_Data.MAC_Address) CONCAT(punctuation_marks,Switch_Parameter.Switch_Data.MAC_Address,Switch_Parameter.Switch_Data.MAC_Address) ,CONCAT(MAC_StringArray[2],Switch_Parameter.Switch_Data.MAC_Address,Switch_Parameter.Switch_Data.MAC_Address) CONCAT(MAC_StringArray[3],Switch_Parameter.Switch_Data.MAC_Address,Switch_Parameter.Switch_Data.MAC_Address) CONCAT(punctuation_marks,Switch_Parameter.Switch_Data.MAC_Address,Switch_Parameter.Switch_Data.MAC_Address) ,CONCAT(MAC_StringArray[0],Switch_Parameter.Switch_Data.MAC_Address,Switch_Parameter.Switch_Data.MAC_Address) CONCAT(MAC_StringArray[1],Switch_Parameter.Switch_Data.MAC_Address,Switch_Parameter.Switch_Data.MAC_Address) ];
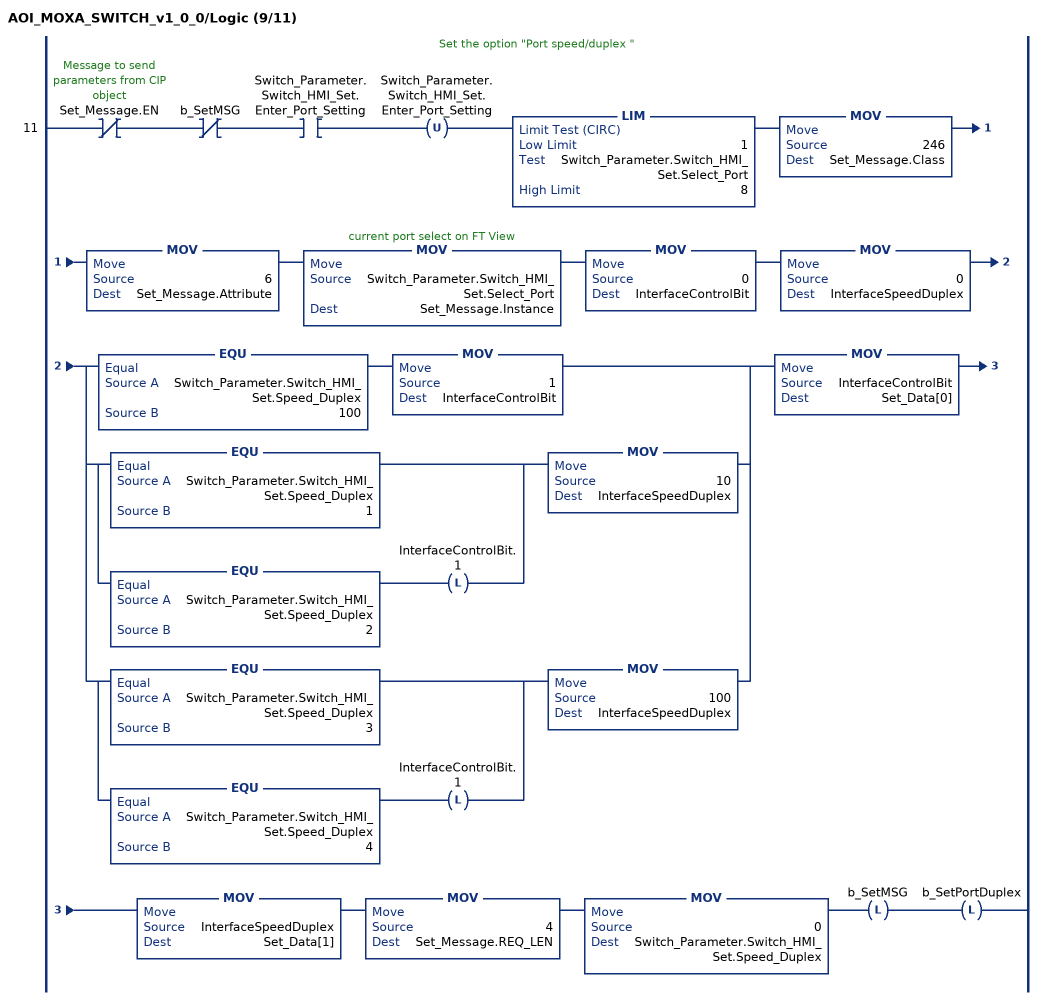
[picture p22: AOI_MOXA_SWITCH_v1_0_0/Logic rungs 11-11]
   // Set the option "Port speed/duplex "
   11: XIO(Set_Message.EN)XIO(b_SetMSG)XIC(Switch_Parameter.Switch_HMI_Set.Enter_Port_Setting)OTU(Switch_Parameter.Switch_HMI_Set.Enter_Port_Setting)LIM(1,Switch_Parameter.Switch_HMI_Set.Select_Port,8)MOV(246,Set_Message.Class)MOV(6,Set_Message.Attribute)MOV(Switch_Parameter.Switch_HMI_Set.Select_Port,Set_Message.Instance)MOV(0,InterfaceControlBit)MOV(0,InterfaceSpeedDuplex)[EQU(Switch_Parameter.Switch_HMI_Set.Speed_Duplex,100) MOV(1,InterfaceControlBit) ,[[EQU(Switch_Parameter.Switch_HMI_Set.Speed_Duplex,1) ,EQU(Switch_Parameter.Switch_HMI_Set.Speed_Duplex,2) OTL(InterfaceControlBit.1) ] MOV(10,InterfaceSpeedDuplex) ,[EQU(Switch_Parameter.Switch_HMI_Set.Speed_Duplex,3) ,EQU(Switch_Parameter.Switch_HMI_Set.Speed_Duplex,4) OTL(InterfaceControlBit.1) ] MOV(100,InterfaceSpeedDuplex) ] ]MOV(InterfaceControlBit,Set_Data[0])MOV(InterfaceSpeedDuplex,Set_Data[1])MOV(4,Set_Message.REQ_LEN)MOV(0,Switch_Parameter.Switch_HMI_Set.Speed_Duplex)OTL(b_SetMSG)OTL(b_SetPortDuplex);
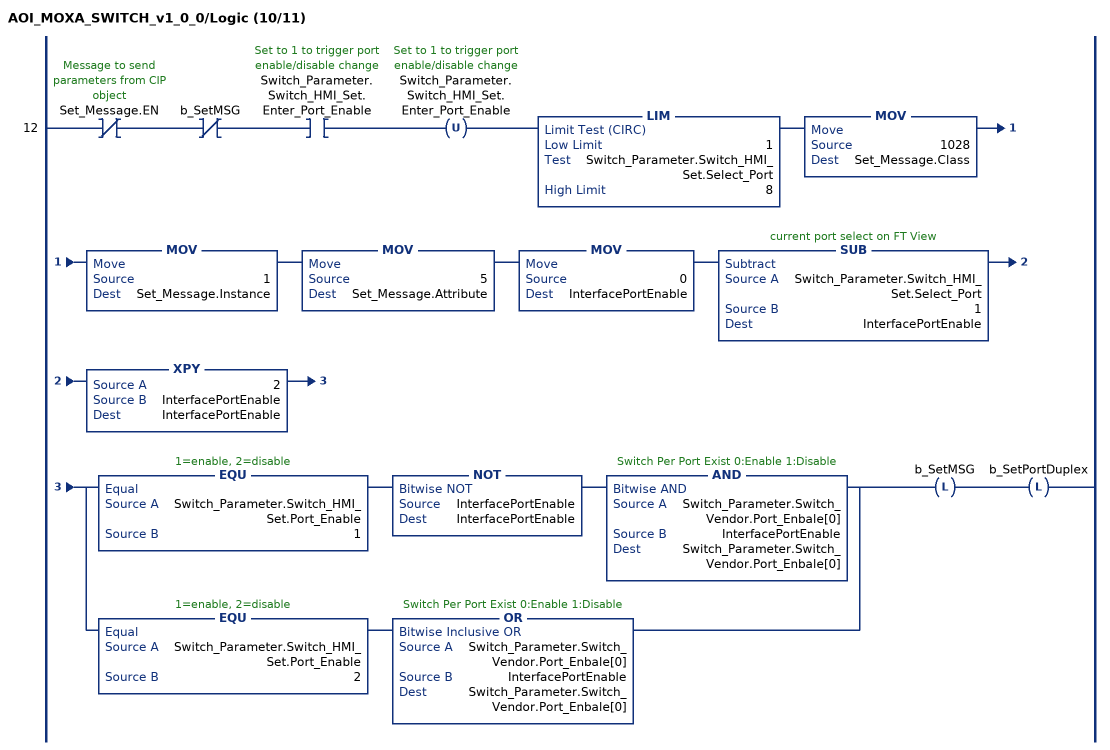
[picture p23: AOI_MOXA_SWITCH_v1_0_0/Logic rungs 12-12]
   12: XIO(Set_Message.EN)XIO(b_SetMSG)XIC(Switch_Parameter.Switch_HMI_Set.Enter_Port_Enable)OTU(Switch_Parameter.Switch_HMI_Set.Enter_Port_Enable)LIM(1,Switch_Parameter.Switch_HMI_Set.Select_Port,8)MOV(1028,Set_Message.Class)MOV(1,Set_Message.Instance)MOV(5,Set_Message.Attribute)MOV(0,InterfacePortEnable)SUB(Switch_Parameter.Switch_HMI_Set.Select_Port,1,InterfacePortEnable)XPY(2,InterfacePortEnable,InterfacePortEnable)[EQU(Switch_Parameter.Switch_HMI_Set.Port_Enable,1) NOT(InterfacePortEnable,InterfacePortEnable) AND(Switch_Parameter.Switch_Vendor.Port_Enbale[0],InterfacePortEnable,Switch_Parameter.Switch_Vendor.Port_Enbale[0]) ,EQU(Switch_Parameter.Switch_HMI_Set.Port_Enable,2) OR(Switch_Parameter.Switch_Vendor.Port_Enbale[0],InterfacePortEnable,Switch_Parameter.Switch_Vendor.Port_Enbale[0]) ]OTL(b_SetMSG)OTL(b_SetPortDuplex);
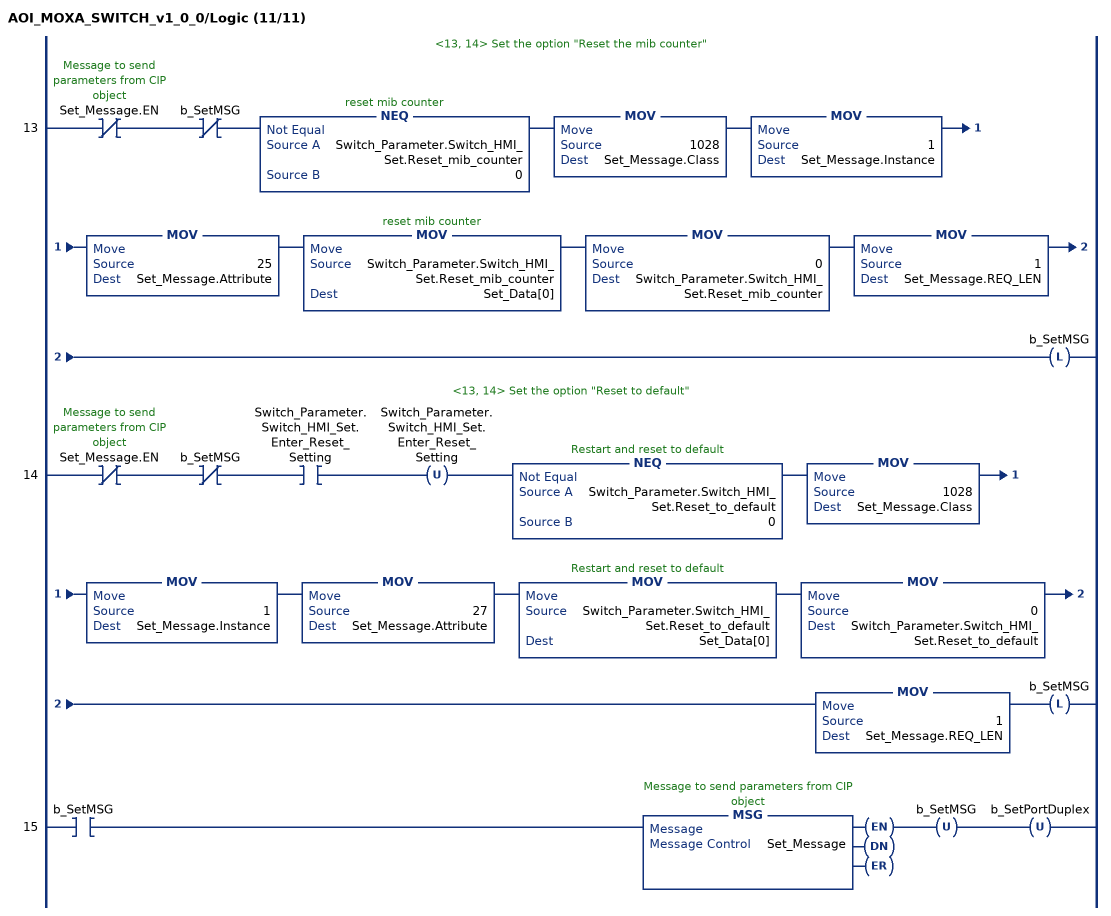
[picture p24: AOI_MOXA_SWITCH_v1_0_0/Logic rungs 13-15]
   // <13, 14> Set the option "Reset the mib counter"
   13: XIO(Set_Message.EN)XIO(b_SetMSG)NEQ(Switch_Parameter.Switch_HMI_Set.Reset_mib_counter,0)MOV(1028,Set_Message.Class)MOV(1,Set_Message.Instance)MOV(25,Set_Message.Attribute)MOV(Switch_Parameter.Switch_HMI_Set.Reset_mib_counter,Set_Data[0])MOV(0,Switch_Parameter.Switch_HMI_Set.Reset_mib_counter)MOV(1,Set_Message.REQ_LEN)OTL(b_SetMSG);
   // <13, 14> Set the option "Reset to default"
   14: XIO(Set_Message.EN)XIO(b_SetMSG)XIC(Switch_Parameter.Switch_HMI_Set.Enter_Reset_Setting)OTU(Switch_Parameter.Switch_HMI_Set.Enter_Reset_Setting)NEQ(Switch_Parameter.Switch_HMI_Set.Reset_to_default,0)MOV(1028,Set_Message.Class)MOV(1,Set_Message.Instance)MOV(27,Set_Message.Attribute)MOV(Switch_Parameter.Switch_HMI_Set.Reset_to_default,Set_Data[0])MOV(0,Switch_Parameter.Switch_HMI_Set.Reset_to_default)MOV(1,Set_Message.REQ_LEN)OTL(b_SetMSG);
   15: XIC(b_SetMSG)MSG(Set_Message)OTU(b_SetMSG)OTU(b_SetPortDuplex);
END_ROUTINE
END_ADD_ON_INSTRUCTION

VAR_GLOBAL   (* controller tags *)
   aoi_switch_instance : AOI_MOXA_SWITCH_v1_0_0;
   MOXA_allstorage : SINT[200];
   MOXA_GetMSG : MESSAGE;
        MessageParameters(ServiceCode := 16#0001, DestinationTag := MOXA_allstorage[0], ...)
   MOXA_GetSingle : MESSAGE;
        MessageParameters(ServiceCode := 16#000e, DestinationTag := MOXA_singlestorage[0], ...)
   moxa_param : MOXA_Switch_Parameter;
   MOXA_SetData : INT[2];
   MOXA_SetMSG : MESSAGE;
        MessageParameters(ServiceCode := 16#0010, LocalElement := MOXA_SetData[0], ...)
   MOXA_singlestorage : SINT[70];
END_VAR

PROGRAM MainProgram   (* main routine MainRoutine *)

ROUTINE MainRoutine   (* ladder *)
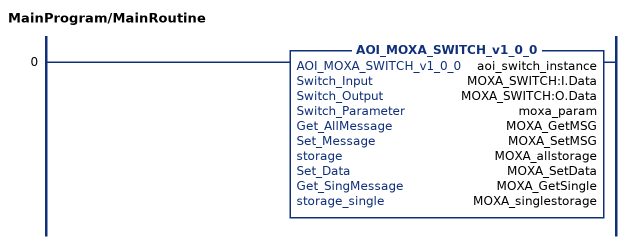
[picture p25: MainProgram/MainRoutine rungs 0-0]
   0: AOI_MOXA_SWITCH_v1_0_0(aoi_switch_instance,MOXA_SWITCH:I.Data,MOXA_SWITCH:O.Data,moxa_param,MOXA_GetMSG,MOXA_SetMSG,MOXA_allstorage,MOXA_SetData,MOXA_GetSingle,MOXA_singlestorage);
END_ROUTINE
END_PROGRAM
